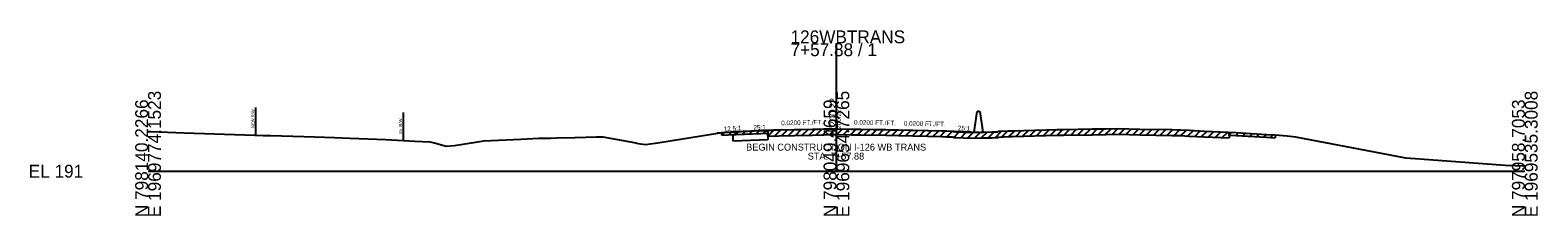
# Model space of a CAD drawing. Extents: x -6494 to 1970605, y -10 to 798140.
# Drawn here: x -25.7 to 302.8, y -9.7 to 30.7 of the extents above; entities that cross this region are included whole.
import ezdxf

# ---------------------------------------------------------------- set-up
doc = ezdxf.new("R2010")
doc.units = 0
for name, color, linetype in [('RD_GPK_XS_Cell', 7, 'Continuous'), ('RD_XS_Base', 7, 'Continuous'), ('RD_XS_EarthShd', 7, 'Continuous'), ('RD_XS_ExGround', 7, 'Continuous'), ('RD_XS_ExPaveRet', 7, 'Continuous'), ('RD_XS_ExRW', 7, 'Continuous'), ('RD_XS_MedBWall', 7, 'Continuous'), ('RD_XS_Misc_Line', 7, 'Continuous'), ('RD_XS_NewRW', 7, 'Continuous'), ('RD_XS_Pave', 7, 'Continuous'), ('RD_XS_PaveOvlay', 7, 'Continuous'), ('RD_XS_PaveShd', 7, 'Continuous'), ('RD_XS_TX_Elev_EX', 7, 'Continuous'), ('RD_XS_TX_Elev_PR', 7, 'Continuous'), ('RD_XS_TX_Notes', 7, 'Continuous'), ('RD_XS_TX_Profile', 7, 'Continuous'), ('RD_XS_TX_ShdSlope', 7, 'Continuous'), ('RD_XS_TX_Slope', 7, 'Continuous')]:
    doc.layers.add(name, color=color, linetype=linetype)

msp = doc.modelspace()

# ---------------------------------------------------------------- linework, layer by layer
at = {"layer": 'RD_GPK_XS_Cell'}
for p, q in [((150, 0), (150, 27.81)), ((0, 0), (150, 0)), ((150, 0), (300, 0))]:
    msp.add_line(p, q, dxfattribs=at)
at = {"layer": 'RD_XS_Base'}
for p, q in [((127.5, 8), (128, 8.02)), ((127.5, 6.52), (127.5, 8)), ((135.06, 6.83), (127.5, 6.52)), ((128, 8.02), (128, 8.58))]:
    msp.add_line(p, q, dxfattribs=at)
at = {"layer": 'RD_XS_EarthShd'}
msp.add_line((128, 8.58), (124.01, 8.27), dxfattribs=at)
at = {"layer": 'RD_XS_ExGround'}
msp.add_lwpolyline([(0, 8.63), (0.63, 8.62), (7.88, 8.35), (23.23, 7.83), (25.09, 7.78), (26.77, 7.73), (36.31, 7.45), (40.61, 7.32), (43.97, 7.19), (51.79, 6.89), (58.15, 6.52), (61.39, 6.42), (62.38, 6.15), (64.94, 5.42), (66.74, 5.62), (73.15, 6.58), (81.25, 6.96), (85.15, 7.15), (87.78, 7.21), (89.03, 7.24), (93.01, 7.34), (97.7, 7.44), (99.12, 7.46), (105.93, 6.21), (106.79, 6.05), (108.4, 5.78), (111.49, 6.26), (125.06, 8.43), (126.41, 8.5), (133.5, 8.83), (134.93, 8.88), (137.48, 8.96), (140.86, 9.03), (144.79, 9.11), (147.22, 9.18), (148.63, 9.21), (149.33, 9.24), (150, 9.22), (153.23, 9.17), (154.01, 9.15), (155.31, 9.13), (160.73, 9.05), (163.51, 8.99), (172.99, 8.8), (173.98, 8.75), (175.26, 8.7), (175.48, 8.61), (176.02, 8.58), (179.38, 8.4), (181.4, 8.47), (182.1, 8.48), (183.96, 8.53), (185.16, 8.56), (185.38, 8.68), (187.45, 8.76), (188.38, 8.79), (198, 9.05), (199.48, 9.09), (205.78, 9.18), (208.67, 9.23), (211.37, 9.27), (216.12, 9.15), (223.06, 9.04), (224.59, 9), (224.97, 9), (226.83, 8.9), (230.21, 8.73), (237.07, 8.42), (243.7, 8.01), (245.57, 7.89), (248.24, 7.66), (250.04, 7.47), (267.15, 4.21), (274.01, 2.92), (277.14, 2.69), (295.72, 1.34), (300, 1.17)], dxfattribs=at)
at = {"layer": 'RD_XS_ExPaveRet'}
for p, q in [((125.06, 7.81), (125.06, 8.43)), ((125.06, 7.81), (126.41, 7.87)), ((126.41, 7.87), (133.5, 8.21)), ((133.5, 8.21), (134.93, 8.26)), ((134.93, 8.26), (135.06, 8.26)), ((135.06, 7.64), (135.06, 8.89)), ((135.06, 8.89), (135.06, 8.26)), ((135.06, 7.64), (137.48, 7.71)), ((137.48, 7.71), (140.86, 7.78)), ((140.86, 7.78), (144.79, 7.86)), ((144.79, 7.86), (147.22, 7.93)), ((147.22, 7.93), (148.63, 7.96)), ((148.63, 7.96), (149.33, 7.99)), ((149.33, 7.99), (150, 7.97)), ((150, 7.97), (153.23, 7.92)), ((153.23, 7.92), (154.01, 7.9)), ((154.01, 7.9), (155.31, 7.88)), ((155.31, 7.88), (160.73, 7.8)), ((160.73, 7.8), (163.51, 7.74)), ((163.51, 7.74), (172.99, 7.55)), ((172.99, 7.55), (173.98, 7.5)), ((173.98, 7.5), (175.26, 7.45)), ((175.26, 7.45), (175.48, 7.36)), ((175.48, 7.36), (176.02, 7.33)), ((176.02, 7.33), (179.38, 7.15)), ((179.38, 7.15), (181.4, 7.22)), ((181.4, 7.22), (182.1, 7.23)), ((182.1, 7.23), (183.96, 7.28)), ((183.96, 7.28), (185.16, 7.31)), ((185.16, 7.31), (185.38, 7.43)), ((185.38, 7.43), (187.45, 7.51)), ((187.45, 7.51), (188.38, 7.54)), ((188.38, 7.54), (198, 7.8)), ((198, 7.8), (199.48, 7.84)), ((199.48, 7.84), (205.78, 7.93)), ((205.78, 7.93), (208.67, 7.98)), ((208.67, 7.98), (211.37, 8.02)), ((211.37, 8.02), (216.12, 7.9)), ((216.12, 7.9), (223.06, 7.79)), ((223.06, 7.79), (224.59, 7.75)), ((224.59, 7.75), (224.97, 7.75)), ((224.97, 7.75), (226.83, 7.65)), ((226.83, 7.65), (230.21, 7.48)), ((230.21, 7.48), (235.57, 7.23)), ((235.57, 8.48), (235.57, 7.23)), ((235.57, 7.86), (235.57, 8.48)), ((235.57, 7.86), (237.07, 7.79)), ((237.07, 7.79), (243.7, 7.38)), ((243.7, 7.38), (245.57, 7.26)), ((245.57, 7.89), (245.57, 7.26))]:
    msp.add_line(p, q, dxfattribs=at)
at = {"layer": 'RD_XS_ExRW'}
msp.add_line((55.6, 12.79), (55.6, 6.79), dxfattribs=at)
at = {"layer": 'RD_XS_MedBWall'}
for p, q in [((180, 8.48), (180.67, 12.96)), ((181, 12.96), (180.67, 12.96)), ((181, 12.96), (181.33, 12.96)), ((182, 8.48), (181.33, 12.96))]:
    msp.add_line(p, q, dxfattribs=at)
at = {"layer": 'RD_XS_Misc_Line'}
for p, q in [((125.06, 7.81), (125.71, 8.46)), ((126.56, 7.88), (127.22, 8.53)), ((128.06, 7.95), (128.72, 8.6)), ((129.56, 8.02), (130.22, 8.68)), ((131.06, 8.09), (131.72, 8.75)), ((132.56, 8.16), (133.22, 8.82)), ((134.06, 8.23), (134.71, 8.88)), ((135.06, 7.64), (136.35, 8.93)), ((136.56, 7.68), (137.85, 8.97)), ((138.06, 7.72), (139.34, 9)), ((139.56, 7.75), (140.84, 9.03)), ((141.06, 7.78), (142.34, 9.06)), ((142.56, 7.81), (143.84, 9.09)), ((144.06, 7.85), (145.34, 9.13)), ((145.56, 7.88), (146.85, 9.17)), ((147.06, 7.92), (148.34, 9.21)), ((148.56, 7.96), (149.83, 9.23)), ((150.06, 7.97), (151.29, 9.2)), ((151.56, 7.95), (152.79, 9.18)), ((153.06, 7.92), (154.29, 9.15)), ((154.56, 7.9), (155.79, 9.13)), ((156.06, 7.87), (157.29, 9.1)), ((157.56, 7.85), (158.79, 9.08)), ((159.06, 7.82), (160.29, 9.05)), ((160.56, 7.8), (161.79, 9.02)), ((162.06, 7.77), (163.29, 8.99)), ((163.57, 7.74), (164.79, 8.96)), ((165.07, 7.71), (166.29, 8.93)), ((166.57, 7.68), (167.79, 8.9)), ((168.07, 7.65), (169.29, 8.87)), ((169.57, 7.62), (170.79, 8.84)), ((171.07, 7.59), (172.29, 8.81)), ((172.57, 7.56), (173.77, 8.76)), ((174.07, 7.5), (175.27, 8.7)), ((175.57, 7.35), (176.76, 8.54)), ((177.07, 7.27), (178.25, 8.46)), ((178.57, 7.19), (179.79, 8.41)), ((180.07, 7.17), (181.36, 8.46)), ((181.57, 7.22), (182.85, 8.5)), ((183.07, 7.25), (184.35, 8.54)), ((184.57, 7.29), (185.98, 8.7)), ((186.07, 7.46), (187.36, 8.75)), ((187.57, 7.51), (188.86, 8.8)), ((189.07, 7.56), (190.35, 8.84)), ((190.57, 7.6), (191.85, 8.88)), ((192.07, 7.64), (193.36, 8.92)), ((193.57, 7.68), (194.86, 8.96)), ((195.07, 7.72), (196.36, 9.01)), ((196.57, 7.76), (197.86, 9.05)), ((198.07, 7.8), (199.36, 9.09)), ((199.57, 7.84), (200.84, 9.11)), ((201.07, 7.86), (202.34, 9.13)), ((202.57, 7.88), (203.84, 9.15)), ((204.07, 7.9), (205.34, 9.17)), ((205.57, 7.92), (206.84, 9.19)), ((207.07, 7.95), (208.34, 9.22)), ((208.57, 7.97), (209.84, 9.24)), ((210.07, 8), (211.34, 9.27)), ((211.57, 8.01), (212.79, 9.23)), ((213.07, 7.98), (214.29, 9.2)), ((214.57, 7.94), (215.79, 9.16)), ((216.07, 7.9), (217.3, 9.13)), ((217.57, 7.88), (218.8, 9.11)), ((219.07, 7.86), (220.31, 9.09)), ((220.57, 7.83), (221.81, 9.06)), ((222.07, 7.81), (223.3, 9.04)), ((223.57, 7.78), (224.79, 9)), ((225.08, 7.74), (226.26, 8.93)), ((226.58, 7.66), (227.77, 8.85)), ((228.08, 7.58), (229.27, 8.77)), ((229.58, 7.51), (230.77, 8.7)), ((231.08, 7.44), (232.27, 8.63)), ((232.58, 7.37), (233.77, 8.57)), ((234.08, 7.3), (235.27, 8.5)), ((235.57, 7.86), (236.17, 8.46)), ((237.07, 7.79), (237.66, 8.38)), ((238.57, 7.7), (239.16, 8.29)), ((240.07, 7.61), (240.66, 8.2)), ((241.57, 7.51), (242.16, 8.1)), ((243.07, 7.42), (243.66, 8.01)), ((244.57, 7.33), (245.16, 7.91))]:
    msp.add_line(p, q, dxfattribs=at)
at = {"layer": 'RD_XS_NewRW'}
msp.add_line((23.42, 13.82), (23.42, 7.82), dxfattribs=at)
at = {"layer": 'RD_XS_Pave'}
for p, q in [((138, 8.98), (150, 9.22)), ((150, 9.22), (174, 8.74))]:
    msp.add_line(p, q, dxfattribs=at)
at = {"layer": 'RD_XS_PaveOvlay'}
for p, q in [((135.06, 8.89), (137.48, 8.96)), ((135.06, 8.89), (135.06, 6.83)), ((137.48, 8.96), (140.86, 9.03)), ((140.86, 9.03), (144.79, 9.11)), ((144.79, 9.11), (147.22, 9.18)), ((147.22, 9.18), (148.63, 9.21)), ((148.63, 9.21), (149.33, 9.24)), ((149.33, 9.24), (150, 9.22)), ((150, 9.22), (153.23, 9.17)), ((153.23, 9.17), (154.01, 9.15)), ((154.01, 9.15), (155.31, 9.13)), ((155.31, 9.13), (160.73, 9.05)), ((160.73, 9.05), (163.51, 8.99)), ((163.51, 8.99), (172.99, 8.8)), ((172.99, 8.8), (173.98, 8.75)), ((173.98, 8.75), (175.26, 8.7)), ((175.26, 8.7), (175.48, 8.61)), ((175.48, 8.61), (176.02, 8.58)), ((176.02, 8.58), (179.38, 8.4)), ((179.38, 8.4), (181, 8.45))]:
    msp.add_line(p, q, dxfattribs=at)
at = {"layer": 'RD_XS_PaveShd'}
for p, q in [((138, 8.98), (128, 8.58)), ((174, 8.74), (181, 8.46)), ((181, 8.45), (181, 8.46))]:
    msp.add_line(p, q, dxfattribs=at)

# ---------------------------------------------------------------- texts
at = {"layer": 'RD_GPK_XS_Cell'}
for s, p in [('126WBTRANS', (140, 27.81)), ('7+57.88 / 1', (140, 25.01)), ('EL 191', (-26, -1.4))]:
    msp.add_text(s, height=2.8, dxfattribs=at).set_placement(p)
for s, p in [('E 1969774.1523', (2.8, -10)), ('E 1969654.7265', (152.8, -10)), ('E 1969535.3008', (302.8, -10)), ('N 798140.2266', (0, -10)), ('N 798049.4659', (150, -10)), ('N 797958.7053', (300, -10))]:
    msp.add_text(s, height=2.8, rotation=90, dxfattribs=at).set_placement(p)
at = {"layer": 'RD_XS_ExRW'}
msp.add_text('Ex. R/W ', height=0.65, rotation=90, dxfattribs=at).set_placement((55.35, 8.17))
at = {"layer": 'RD_XS_NewRW'}
msp.add_text('NEW R/W ', height=0.65, rotation=90, dxfattribs=at).set_placement((23.15, 9.38))
at = {"layer": 'RD_XS_TX_Elev_EX'}
msp.add_text('200.22', height=1, rotation=90, dxfattribs=at).set_placement((151, 9.22))
at = {"layer": 'RD_XS_TX_Elev_PR'}
msp.add_text(' 200.22', height=1.5, rotation=90, dxfattribs=at).set_placement((150, 9.22))
at = {"layer": 'RD_XS_TX_Notes'}
for s, p in [('BEGIN CONSTRUCTION I-126 WB TRANS', (130.32, 4.48)), ('STA. 7+57.88', (143.73, 2.52))]:
    msp.add_text(s, height=1.5, dxfattribs=at).set_placement(p)
at = {"layer": 'RD_XS_TX_Profile'}
for rotation, p in [(2.2906, (131.94, 8.99)), (357.7094, (176.46, 8.9))]:
    msp.add_text('25:1', height=1, rotation=rotation, dxfattribs=at).set_placement(p)
at = {"layer": 'RD_XS_TX_ShdSlope'}
msp.add_text('12.5:1', height=1, rotation=4.5739, dxfattribs=at).set_placement((125.5, 8.64))
at = {"layer": 'RD_XS_TX_Slope'}
for rotation, p in [(1.1458, (137.98, 9.98)), (358.8542, (153.83, 10.15)), (358.8542, (164.68, 9.92))]:
    msp.add_text('0.0200 FT./FT.', height=1, rotation=rotation, dxfattribs=at).set_placement(p)

doc.saveas('drawing.dxf')
